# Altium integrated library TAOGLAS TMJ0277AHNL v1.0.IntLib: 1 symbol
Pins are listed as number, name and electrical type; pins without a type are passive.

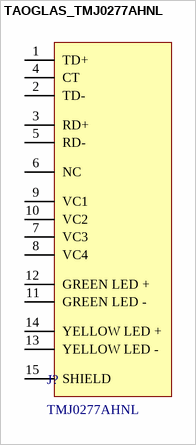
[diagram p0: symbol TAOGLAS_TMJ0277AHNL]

## TAOGLAS_TMJ0277AHNL
designator J?, comment TMJ0277AHNL
RJ45 connector with integrated magnetics 10/100Base-T Single Port Tab-DOWN with right angle THT mount and LEDs; ComponentLibStatus: Created; MFG: Taoglas; Temp_High: +85C; Temp_Low: -40C
footprint TAOGLAS_TMJ0277AHNL (RJ45 connector with integrated magnetics 10/100Base-T Single Port Tab-DOWN with right angle THT mount and LEDs)
pins: 1 TD+, 2 TD-, 3 RD+, 4 CT, 5 RD-, 6 NC, 7 VC3, 8 VC4, 9 VC1, 10 VC2, 11 GREEN LED -, 12 GREEN LED +, 13 YELLOW LED -, 14 YELLOW LED +, 15 SHIELD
